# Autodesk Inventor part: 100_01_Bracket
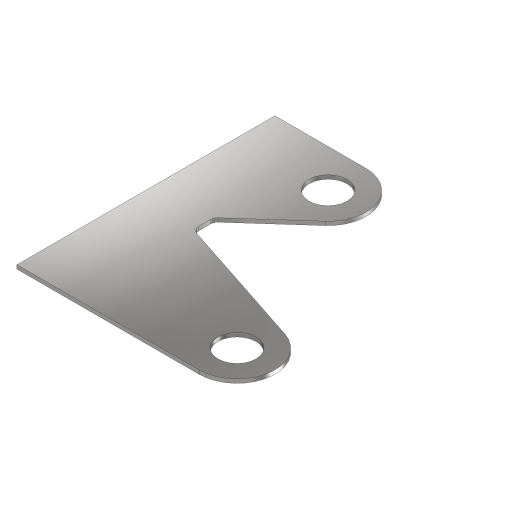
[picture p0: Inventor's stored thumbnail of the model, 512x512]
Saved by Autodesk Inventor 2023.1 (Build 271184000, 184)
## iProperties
Company: Fabian Stasiak CAD Consulting
Category: Autodesk® Inventor® Tutorial Series
Created: 2005-11
Part Number: 100_01_Bracket
Material: Stal
Document SubType Name: Konstrukcje blachowe
Designer: F.Stasiak
Density: 1 g/cm^3
Sheet Metal Rule: Steel 2.5 mm/Round
Appearance: Częściowo polerowany
Catalog Web Link: www.expertbooks.eu
Description: Bracket
FLATAREA: =<FLAT PATTERN AREA>
Author: F.Stasiak
Subject: Sheet Metal Design. Basic and Advanced techniques
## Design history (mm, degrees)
node "Powierzchnia1"
  sketch "Szkic2"
    geometry: L1 (38, -6.765)-(127.798, -36.247); L2 (120, -85)-(0, -85); L3 (76.671, 41.37)-(38, 6.765); L4 (0, 0)-(38, 0); L5 (0, 85)-(60, 85); L6 (0, 85)-(0, -85) reference; L7 (38, 6.765)-(38, -6.765); C1 r 12.5 at (120, -60); C2 r 12.5 at (60, 60); A1 r 25 centre (120, -60) between (120, -85) and (127.798, -36.247); A2 r 25 centre (60, 60) between (76.671, 41.37) and (60, 85); 1 further point
    constraints: 14 end point, 4 centre point, 4 point on circle, 4 tangent, 3 coincident, 2 equal radius, 2 midpoint, 2 parallel, 2 vertical, 1 horizontal, 1 perpendicular, 1 other
    dimensions: "d2" = 170 distance of L5.start L2.end; "d3" = 25 radius of A2; "d4" = 120 distance of L2.start L2.end; "d5" = 60 distance of L5.start L5.end; "d8" = 25 diameter of C2; "d32" = 38 distance of L4.start L4.end; "d34" = 60 deg angle of L3 L1
feature "Zaokrąglenie narożnika1" dims "d31" = 5
node "Bryła1"
node "Korpusy bryłowe"
node "Korpusy powierzchniowe"
feature "Płyta1" dims "d35" = 2.5 (= Thickness)
other parameters: "Thickness" = 2.5 (derived), "BendRadius" = 2.5 (= Thickness), "BendReliefWidth" = 2.5 (= Thickness), "BendReliefDepth" = 1.25 (= 0.5 x Thickness), "SeamGap" = 0.01, "MinimumRemnant" = 5 (= 2 x Thickness), "TransitionRadius" = 2.5 (= BendRadius), "d9" = 2.5 (= BendRadius), "JacobiRadiusSize" = 2.5 (= BendRadius), "GapSize" = 2.5 (= Thickness)
